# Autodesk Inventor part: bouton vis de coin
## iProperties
Shininess: 64.0
Length Units: 11269
Angle Units: 11279
Time Units: 11290
Mass Units: 11283
Length Display Precision: 3
Angle Display Precision: 2
Compacted: True
Part Number: bouton vis de coin
Document SubType Name: Modeling
Created: 2004-12
Material: Par défaut
Designer: LEGERET Philippe
Density: 0.0
Volumn: 0.0
Area: 0.0
PropertySet Name: Model Information
Control State: 0
Master: False
Checked Out: False
Author: LEGERET Philippe
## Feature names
1. Révolution1 [Revolution]
2. Chanfrein1 [Chamfer]
3. Perçage1 [Hole]
